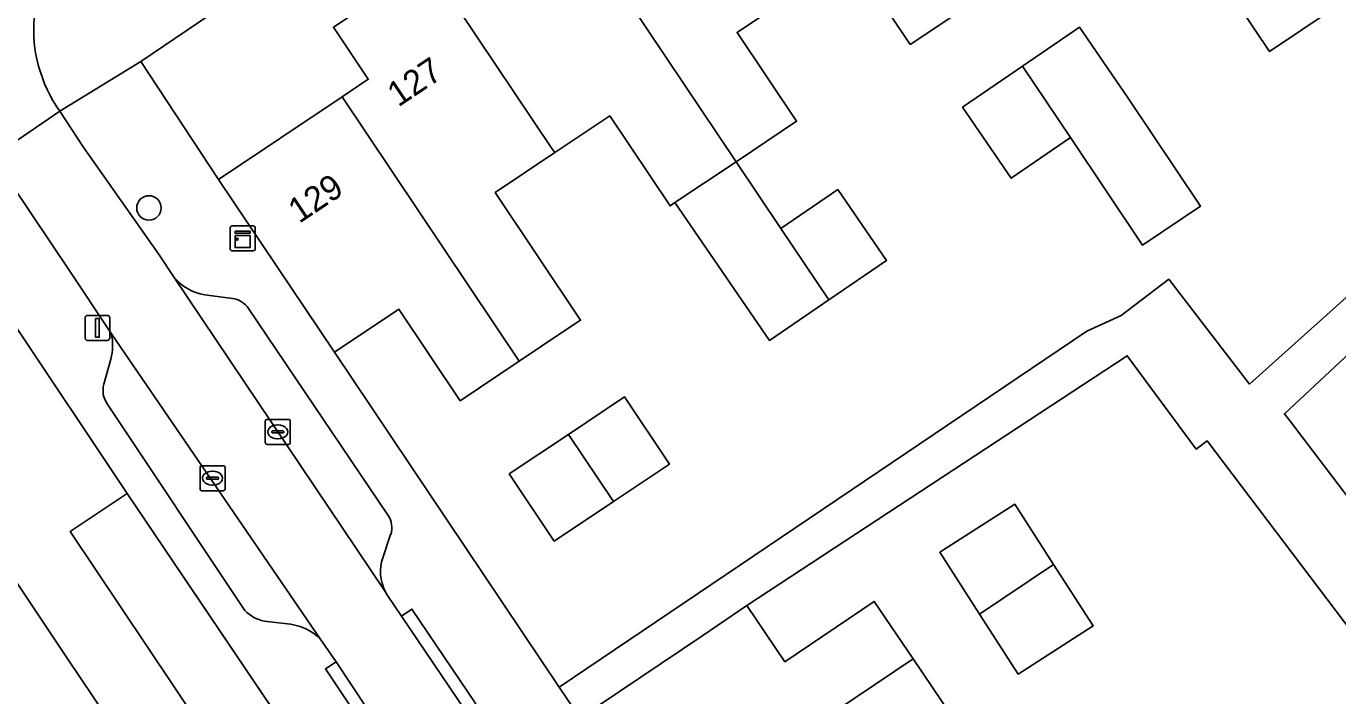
# Model space of a CAD drawing. Extents: x 158352 to 159489, y 383828 to 384603.
# Drawn here: x 158936.2 to 158988.7, y 384253.3 to 384280.1 of the extents above; entities that cross this region are included whole.
import ezdxf

# ---------------------------------------------------------------- set-up
doc = ezdxf.new("R2010")
doc.units = 0
for name, color, linetype in [('IMGEO_Boom', 7, 'Continuous'), ('IMGEO_Erf', 7, 'Continuous'), ('IMGEO_Kast', 7, 'Continuous'), ('IMGEO_Kolk', 7, 'Continuous'), ('IMGEO_Lichtmast', 7, 'Continuous'), ('IMGEO_Muur', 7, 'Continuous'), ('IMGEO_Pand', 7, 'Continuous'), ('IMGEO_Pand_nummerreeks', 7, 'Continuous'), ('IMGEO_Parkeervlak_open', 7, 'Continuous'), ('IMGEO_Rijbaan_lokaal_open', 7, 'Continuous'), ('IMGEO_Voetpad_open', 7, 'Continuous')]:
    doc.layers.add(name, color=color, linetype=linetype)

msp = doc.modelspace()

# ---------------------------------------------------------------- linework, layer by layer
at = {"layer": 'IMGEO_Boom'}
msp.add_circle((158941.13, 384272.801), 0.489, dxfattribs=at)
at = {"layer": 'IMGEO_Erf'}
for points in [[(158986.492, 384283.295), (158984.581, 384286.148), (158987.459, 384288.074), (158989.369, 384285.222), (158988.812, 384284.849), (158990.615, 384282.157), (158988.591, 384280.801), (158986.003, 384279.068), (158984.2, 384281.76)], [(158976.11, 384278.481), (158978.385, 384280.041), (158980.332, 384277.201), (158983.234, 384272.871), (158980.911, 384271.315), (158978.027, 384275.62), (158975.657, 384273.994), (158973.709, 384276.835)], [(158957.923, 384263.731), (158960.168, 384265.235), (158961.971, 384262.543), (158959.726, 384261.039), (158957.359, 384259.454), (158955.556, 384262.146)], [(158940.261, 384261.367), (158937.976, 384259.839), (158944.137, 384250.629), (158946.253, 384252.074), (158949.005, 384247.96), (158949.206, 384248.095), (158949.172, 384248.145)], [(158974.392, 384256.523), (158972.794, 384259.005), (158975.794, 384260.936), (158977.354, 384258.513), (158978.933, 384256.06), (158975.934, 384254.129)]]:
    msp.add_lwpolyline(points, close=True, dxfattribs=at)
for points in [[(158953.222, 384287.087), (158940.799, 384278.671), (158943.919, 384273.946), (158948.863, 384277.257), (158949.909, 384277.957), (158948.515, 384280.038), (158952.317, 384282.584)], [(158974.316, 384281.16), (158971.616, 384279.352), (158969.245, 384282.893)], [(158967.101, 384281.457), (158964.676, 384279.833), (158967.059, 384276.274), (158964.64, 384274.654), (158966.434, 384271.975), (158968.709, 384273.535), (158970.656, 384270.695), (158968.351, 384269.114), (158965.981, 384267.488), (158962.191, 384273.015), (158961.996, 384272.884), (158959.58, 384276.491), (158957.38, 384275.018), (158954.989, 384273.417), (158958.412, 384268.305), (158957.747, 384267.86), (158955.959, 384266.663), (158953.591, 384265.078), (158951.137, 384268.742), (158948.56, 384267.017), (158957.557, 384253.607), (158978.687, 384267.866), (158980.054, 384268.49), (158981.964, 384269.947), (158985.203, 384265.743), (159003.905, 384282.542)], [(158996.307, 384273.622), (158986.598, 384264.555), (158986.787, 384264.307), (158989.753, 384260.415)], [(158993.796, 384249.884), (158983.504, 384263.466), (158983.065, 384263.142), (158980.303, 384266.882), (158965.072, 384256.872), (158966.593, 384254.621), (158970.171, 384257.038), (158971.728, 384254.733), (158973.279, 384252.437)]]:
    msp.add_lwpolyline(points, dxfattribs=at)
at = {"layer": 'IMGEO_Kast'}
for p, q in [((158944.384, 384271.159), (158944.384, 384272)), ((158944.384, 384272), (158944.384, 384271.159)), ((158944.459, 384272.084), (158945.3, 384272.084)), ((158945.3, 384272.084), (158944.459, 384272.084)), ((158945.384, 384272.009), (158945.384, 384271.168)), ((158945.384, 384271.168), (158945.384, 384272.009)), ((158945.309, 384271.084), (158944.468, 384271.084)), ((158944.468, 384271.084), (158945.309, 384271.084))]:
    msp.add_line(p, q, dxfattribs=at)
for points in [[(158944.579, 384271.874), (158945.179, 384271.874), (158945.179, 384271.789), (158944.579, 384271.789), (158944.579, 384271.874)], [(158944.579, 384271.699), (158945.179, 384271.699), (158945.179, 384271.21), (158944.579, 384271.21), (158944.579, 384271.699)]]:
    msp.add_lwpolyline(points, dxfattribs=at)
msp.add_circle((158944.663, 384271.548), 0.0377, dxfattribs=at)
for centre, start, end in [((158944.462, 384272.006), 92.4484, 184.2845), ((158944.462, 384272.006), 92.4484, 184.2845), ((158945.306, 384272.006), 2.4484, 94.2845), ((158945.306, 384272.006), 2.4484, 94.2845), ((158944.462, 384271.162), 182.4484, 274.2845), ((158944.462, 384271.162), 182.4484, 274.2845), ((158945.306, 384271.162), 272.4484, 4.2845), ((158945.306, 384271.162), 272.4484, 4.2845)]:
    msp.add_arc(centre, 0.0779, start, end, dxfattribs=at)
at = {"layer": 'IMGEO_Kolk'}
for p, q in [((158945.787, 384263.403), (158945.787, 384264.255)), ((158945.862, 384264.329), (158946.714, 384264.329)), ((158946.046, 384263.823), (158946.046, 384263.835)), ((158946.089, 384263.872), (158946.487, 384263.872)), ((158946.275, 384264.109), (158946.3, 384264.109)), ((158946.53, 384263.835), (158946.53, 384263.823)), ((158946.788, 384264.255), (158946.788, 384263.403)), ((158946.714, 384263.329), (158945.862, 384263.329)), ((158946.484, 384263.786), (158946.086, 384263.786)), ((158946.298, 384263.549), (158946.273, 384263.549)), ((158943.176, 384261.549), (158943.176, 384262.401)), ((158943.251, 384262.475), (158944.103, 384262.475)), ((158944.177, 384262.401), (158944.177, 384261.549)), ((158943.435, 384261.969), (158943.435, 384261.981)), ((158943.873, 384261.932), (158943.475, 384261.932)), ((158943.478, 384262.018), (158943.876, 384262.018)), ((158943.664, 384262.255), (158943.689, 384262.255)), ((158943.919, 384261.981), (158943.919, 384261.969)), ((158944.103, 384261.475), (158943.251, 384261.475)), ((158943.687, 384261.695), (158943.662, 384261.695))]:
    msp.add_line(p, q, dxfattribs=at)
for points in [[(158945.787, 384263.403), (158945.787, 384264.255)], [(158945.862, 384264.329), (158946.714, 384264.329)], [(158946.788, 384264.255), (158946.788, 384263.403)], [(158946.714, 384263.329), (158945.862, 384263.329)], [(158943.176, 384261.549), (158943.176, 384262.401)], [(158943.251, 384262.475), (158944.103, 384262.475)], [(158944.177, 384262.401), (158944.177, 384261.549)], [(158944.103, 384261.475), (158943.251, 384261.475)]]:
    msp.add_lwpolyline(points, dxfattribs=at)
for centre, radius, start, end in [((158945.864, 384264.253), 0.0765, 91.552, 178.448), ((158945.864, 384264.253), 0.0765, 91.552, 178.448), ((158946.086, 384263.832), 0.0403, 85.8775, 175.7526), ((158946.491, 384263.834), 0.0386, 1.7309, 96.639), ((158946.712, 384264.253), 0.0765, 1.552, 88.448), ((158946.712, 384264.253), 0.0765, 1.552, 88.448), ((158945.864, 384263.405), 0.0765, 181.552, 268.448), ((158945.864, 384263.405), 0.0765, 181.552, 268.448), ((158946.083, 384263.822), 0.0366, 178.938, 274.7102), ((158946.487, 384263.829), 0.043, 264.8664, 352.4533), ((158946.712, 384263.405), 0.0765, 271.552, 358.448), ((158946.712, 384263.405), 0.0765, 271.552, 358.448), ((158943.253, 384262.399), 0.0765, 91.552, 178.448), ((158943.253, 384262.399), 0.0765, 91.552, 178.448), ((158944.101, 384262.399), 0.0765, 1.552, 88.448), ((158944.101, 384262.399), 0.0765, 1.552, 88.448), ((158943.475, 384261.978), 0.0403, 85.8775, 175.7526), ((158943.472, 384261.968), 0.0366, 178.938, 274.7102), ((158943.876, 384261.975), 0.043, 264.8664, 352.4533), ((158943.88, 384261.98), 0.0386, 1.7309, 96.639), ((158943.253, 384261.551), 0.0765, 181.552, 268.448), ((158943.253, 384261.551), 0.0765, 181.552, 268.448), ((158944.101, 384261.551), 0.0765, 271.552, 358.448), ((158944.101, 384261.551), 0.0765, 271.552, 358.448)]:
    msp.add_arc(centre, radius, start, end, dxfattribs=at)
for centre, major_axis, ratio, start_param, end_param in [((158946.274, 384263.829), (-0.387, 0.002), 0.722429, 4.712389, 7.853982), ((158946.299, 384263.829), (-0.39, 0.002), 0.717154, 1.570796, 4.712389), ((158943.663, 384261.975), (-0.387, 0.002), 0.722429, 4.712389, 7.853982), ((158943.688, 384261.975), (-0.39, 0.002), 0.717154, 1.570796, 4.712389)]:
    msp.add_ellipse(centre, major_axis=major_axis, ratio=ratio, start_param=start_param, end_param=end_param, dxfattribs=at)
at = {"layer": 'IMGEO_Lichtmast'}
for p, q in [((158938.571, 384267.595), (158938.571, 384268.395)), ((158938.571, 384268.395), (158938.571, 384267.595)), ((158938.671, 384268.495), (158939.461, 384268.495)), ((158939.461, 384268.495), (158938.671, 384268.495)), ((158939.561, 384268.395), (158939.561, 384267.595)), ((158939.561, 384267.595), (158939.561, 384268.395)), ((158939.461, 384267.495), (158938.671, 384267.495)), ((158938.671, 384267.495), (158939.461, 384267.495))]:
    msp.add_line(p, q, dxfattribs=at)
msp.add_lwpolyline([(158938.991, 384268.37), (158939.141, 384268.37), (158939.141, 384267.62), (158938.991, 384267.62), (158938.991, 384268.37)], dxfattribs=at)
for centre, start, end in [((158938.671, 384268.395), 90, 180), ((158938.671, 384268.395), 90, 180), ((158939.461, 384268.395), 0, 90), ((158939.461, 384268.395), 360, 90), ((158938.671, 384267.595), 180, 270), ((158938.671, 384267.595), 180, 270), ((158939.461, 384267.595), 270, 0), ((158939.461, 384267.595), 270, 0)]:
    msp.add_arc(centre, 0.1, start, end, dxfattribs=at)
at = {"layer": 'IMGEO_Muur'}
for points in [[(158948.56, 384267.017), (158957.557, 384253.607)], [(158949.265, 384248.006), (158940.261, 384261.367)]]:
    msp.add_lwpolyline(points, dxfattribs=at)
at = {"layer": 'IMGEO_Pand'}
for points in [[(158962.469, 384288.372), (158967.034, 384281.557), (158967.101, 384281.457), (158969.245, 384282.893), (158971.616, 384279.352), (158974.316, 384281.16), (158967.312, 384291.616)], [(158962.469, 384288.372), (158957.624, 384285.128), (158964.64, 384274.654), (158967.059, 384276.274), (158964.676, 384279.833), (158967.101, 384281.457), (158967.034, 384281.557)], [(158957.624, 384285.128), (158952.783, 384281.887), (158957.268, 384275.185), (158957.38, 384275.018), (158959.58, 384276.491), (158961.996, 384272.884), (158962.191, 384273.015), (158964.64, 384274.654)], [(158986.787, 384283.493), (158986.492, 384283.295), (158984.2, 384281.76), (158986.003, 384279.068), (158988.591, 384280.801)], [(158955.959, 384266.663), (158957.747, 384267.86), (158958.412, 384268.305), (158954.989, 384273.417), (158957.38, 384275.018), (158957.268, 384275.185), (158952.783, 384281.887), (158952.317, 384282.584), (158948.515, 384280.038), (158949.909, 384277.957), (158948.863, 384277.257)], [(158978.027, 384275.62), (158980.911, 384271.315), (158983.234, 384272.871), (158980.332, 384277.201), (158978.385, 384280.041), (158976.11, 384278.481)], [(158978.027, 384275.62), (158976.11, 384278.481), (158973.709, 384276.835), (158975.657, 384273.994)], [(158955.959, 384266.663), (158948.863, 384277.257), (158943.919, 384273.946), (158948.56, 384267.017), (158951.137, 384268.742), (158953.591, 384265.078)], [(158966.434, 384271.975), (158964.64, 384274.654), (158962.191, 384273.015), (158965.981, 384267.488), (158968.351, 384269.114)], [(158966.434, 384271.975), (158968.351, 384269.114), (158970.656, 384270.695), (158968.709, 384273.535)], [(158930.912, 384265.149), (158937.861, 384254.768), (158941.052, 384250), (158941.716, 384249.009), (158943.197, 384250), (158944.137, 384250.629), (158937.976, 384259.839), (158940.261, 384261.367), (158935.621, 384268.3)], [(158930.912, 384265.149), (158929.916, 384264.482), (158928.539, 384266.54), (158924.927, 384264.123), (158925.377, 384263.451), (158929.925, 384256.656), (158929.999, 384256.546), (158932.115, 384257.962), (158935.497, 384252.909), (158937.496, 384250.25), (158939.375, 384247.442), (158939.982, 384247.848), (158941.358, 384248.769), (158941.716, 384249.009), (158941.052, 384250), (158937.861, 384254.768)], [(158957.923, 384263.731), (158959.726, 384261.039), (158961.971, 384262.543), (158960.168, 384265.235)], [(158957.923, 384263.731), (158955.556, 384262.146), (158957.359, 384259.454), (158959.726, 384261.039)], [(158977.354, 384258.513), (158975.794, 384260.936), (158972.794, 384259.005), (158974.392, 384256.523)], [(158977.354, 384258.513), (158974.392, 384256.523), (158975.934, 384254.129), (158978.933, 384256.06)], [(158971.728, 384254.733), (158970.171, 384257.038), (158966.593, 384254.621), (158965.072, 384256.872), (158963.302, 384255.677), (158959.158, 384252.878), (158961.1, 384250), (158961.499, 384249.409), (158962.123, 384248.483), (158962.218, 384248.343), (158964.684, 384250)], [(158969.761, 384250), (158973.279, 384252.437), (158971.728, 384254.733), (158964.684, 384250), (158962.218, 384248.343), (158961.44, 384247.82), (158964.426, 384243.377), (158964.714, 384243.57), (158970.609, 384247.531), (158971.168, 384247.907)]]:
    msp.add_lwpolyline(points, close=True, dxfattribs=at)
at = {"layer": 'IMGEO_Parkeervlak_open'}
for points in [[(158942.113, 384270.058), (158950.589, 384257.44)], [(158944.478, 384269.175), (158943.368, 384269.326)], [(158950.706, 384260.485), (158945.119, 384268.776)], [(158947.99, 384255.54), (158939.624, 384267.764)], [(158939.604, 384266.748), (158939.326, 384265.737)], [(158939.456, 384264.96), (158944.973, 384256.669)], [(158950.492, 384258.789), (158950.808, 384259.719)], [(158945.747, 384256.247), (158946.804, 384256.122)]]:
    msp.add_lwpolyline(points, dxfattribs=at)
for centre, radius, start, end in [((158943.63, 384271.217), 1.909, 217.3767, 262.1161), ((158944.361, 384268.272), 0.91, 33.5924, 82.6059), ((158937.506, 384267.297), 2.169, 345.3233, 12.4213), ((158940.185, 384265.481), 0.896, 163.4154, 215.581), ((158949.987, 384259.999), 0.868, 341.1366, 34.0331), ((158952.126, 384258.229), 1.728, 161.073, 207.1525), ((158946.051, 384257.726), 1.51, 224.4285, 258.3713), ((158946.455, 384253.911), 2.239, 46.7005, 81.0228)]:
    msp.add_arc(centre, radius, start, end, dxfattribs=at)
at = {"layer": 'IMGEO_Rijbaan_lokaal_open'}
msp.add_lwpolyline([(158933.238, 384277.293), (158934.878, 384274.851), (158937.565, 384276.679)], dxfattribs=at)
msp.add_lwpolyline([(158942.113, 384270.058), (158941.545, 384270.918), (158938.496, 384275.255), (158937.565, 384276.679), (158934.878, 384274.851), (158937.931, 384270.305), (158939.624, 384267.764), (158947.99, 384255.54), (158948.621, 384254.614), (158951.135, 384250.832), (158953.801, 384252.656), (158951.242, 384256.449), (158950.688, 384257.27), (158950.589, 384257.44)], close=True, dxfattribs=at)
msp.add_arc((158942.143, 384279.951), 5.627, 135.2467, 215.5538, dxfattribs=at)
at = {"layer": 'IMGEO_Voetpad_open'}
for points in [[(158937.565, 384276.679), (158940.799, 384278.671), (158953.222, 384287.087), (158982.278, 384306.539)], [(159003.905, 384282.542), (158985.203, 384265.743), (158981.964, 384269.947), (158980.054, 384268.49), (158978.687, 384267.866), (158957.557, 384253.607), (158958.391, 384252.364), (158959.158, 384252.878), (158963.302, 384255.677), (158965.072, 384256.872), (158980.303, 384266.882), (158983.065, 384263.142), (158983.504, 384263.466), (158993.796, 384249.884)], [(158958.391, 384252.364), (158957.557, 384253.607), (158948.56, 384267.017), (158943.919, 384273.946), (158940.799, 384278.671), (158937.565, 384276.679), (158938.496, 384275.255), (158941.545, 384270.918), (158942.113, 384270.058)], [(158939.624, 384267.764), (158937.931, 384270.305), (158934.878, 384274.851)], [(158989.753, 384260.415), (158986.787, 384264.307), (158986.598, 384264.555), (158996.307, 384273.622)], [(158943.368, 384269.326), (158944.478, 384269.175)], [(158945.119, 384268.776), (158950.706, 384260.485)], [(158935.621, 384268.3), (158940.261, 384261.367), (158949.172, 384248.145), (158949.206, 384248.095), (158949.265, 384248.006), (158950.103, 384246.763), (158953.05, 384242.388), (158953.16, 384242.224), (158956.145, 384237.782), (158956.258, 384237.614), (158956.001, 384237.441), (158958.873, 384233.166), (158961.764, 384228.864), (158962.028, 384229.041), (158962.121, 384228.902), (158965.106, 384224.46), (158965.19, 384224.335), (158968.154, 384219.911), (158969.084, 384218.523), (158971.862, 384214.376), (158979.183, 384203.447), (158983.795, 384196.582), (158985.981, 384193.365), (158986.851, 384190.812)], [(158939.326, 384265.737), (158939.604, 384266.748)], [(158944.973, 384256.669), (158939.456, 384264.96)], [(158950.808, 384259.719), (158950.492, 384258.789)], [(158950.589, 384257.44), (158950.688, 384257.27), (158951.242, 384256.449), (158951.656, 384256.728), (158954.215, 384252.935), (158953.801, 384252.656), (158955.463, 384250.193), (158955.623, 384249.999)], [(158946.804, 384256.122), (158945.747, 384256.247)], [(158948.205, 384254.338), (158948.621, 384254.614), (158947.99, 384255.54)], [(158952.78, 384248.358), (158951.688, 384250), (158951.135, 384250.832), (158950.719, 384250.556), (158948.205, 384254.338)]]:
    msp.add_lwpolyline(points, dxfattribs=at)
for points in [[(158953.801, 384252.656), (158954.215, 384252.935), (158951.656, 384256.728), (158951.242, 384256.449)], [(158948.621, 384254.614), (158948.205, 384254.338), (158950.719, 384250.556), (158951.135, 384250.832)]]:
    msp.add_lwpolyline(points, close=True, dxfattribs=at)
for centre, radius, start, end in [((158942.143, 384279.951), 5.627, 135.2467, 215.5538), ((158943.63, 384271.217), 1.909, 217.3767, 262.1161), ((158944.361, 384268.272), 0.91, 33.5924, 82.6059), ((158937.506, 384267.297), 2.169, 345.3233, 12.4213), ((158940.185, 384265.481), 0.896, 163.4154, 215.581), ((158949.987, 384259.999), 0.868, 341.1366, 34.0331), ((158952.126, 384258.229), 1.728, 161.073, 207.1525), ((158946.051, 384257.726), 1.51, 224.4285, 258.3713), ((158946.455, 384253.911), 2.239, 46.7005, 81.0228)]:
    msp.add_arc(centre, radius, start, end, dxfattribs=at)

# ---------------------------------------------------------------- texts
at = {"layer": 'IMGEO_Pand_nummerreeks'}
for s, rotation, p in [('127', 33.8055, (158951.113, 384276.821)), ('129', 33.7889, (158947.145, 384272.158))]:
    msp.add_text(s, height=1, rotation=rotation, dxfattribs=at).set_placement(p)

doc.saveas('drawing.dxf')
